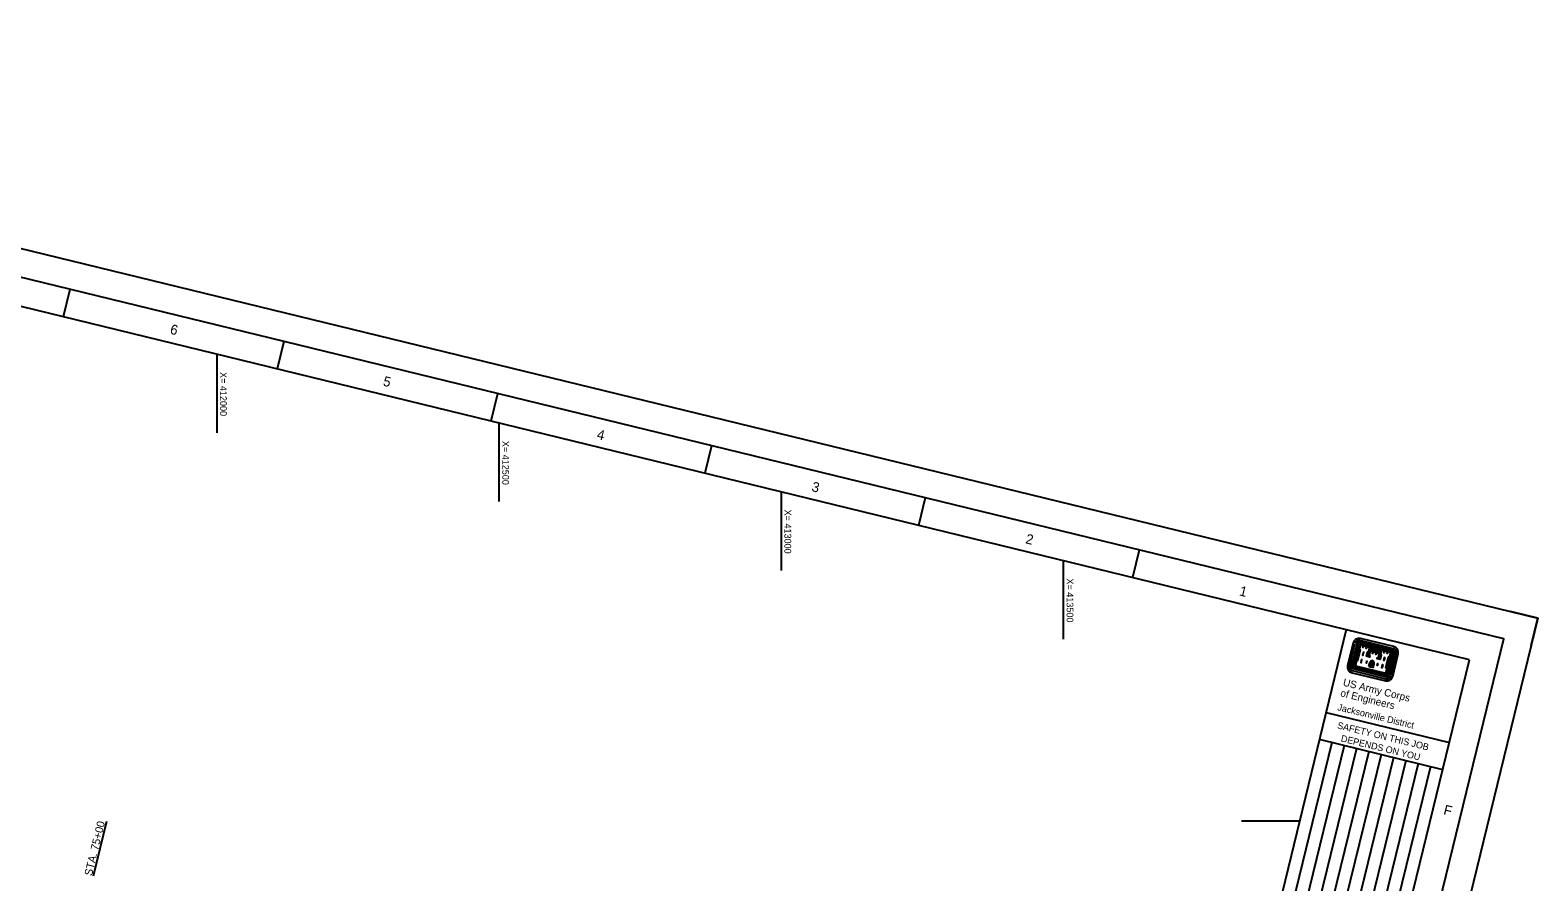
# Model space of a CAD drawing. Extents: x 409260 to 414340, y 1188556 to 1192902.
# Drawn here: x 411669 to 414340, y 1191392 to 1192902 of the extents above; entities that cross this region are included whole.
import ezdxf

# ---------------------------------------------------------------- set-up
doc = ezdxf.new("R2010")
doc.units = 0
for name, color, linetype in [('G-ANNO-NPLT', 7, 'Continuous'), ('G-ANNO-TEXT-LOGO', 7, 'Continuous'), ('G-ANNO-TEXT-TTLB', 7, 'Continuous'), ('G-ANNO-TTLB', 7, 'Continuous'), ('V-ALGN-TEXT', 7, 'Continuous'), ('V-TOPO-COOR-STAT', 7, 'Continuous')]:
    doc.layers.add(name, color=color, linetype=linetype)

msp = doc.modelspace()

# ---------------------------------------------------------------- linework, layer by layer
at = {"layer": 'G-ANNO-NPLT'}
msp.add_lwpolyline([(410065.6, 1192901.9), (414340.3, 1191859.4), (413534.7, 1188556.2), (409260, 1189598.7)], close=True, dxfattribs=at)
msp.add_lwpolyline([(414328.4, 1191810.8), (414340.3, 1191859.4), (414291.7, 1191871.2)], dxfattribs=at)
at = {"layer": 'G-ANNO-TEXT-LOGO'}
for p, q in [((414012.9, 1191815.6), (414003.2, 1191775.8)), ((414006.3, 1191775), (414016, 1191814.8)), ((414019.4, 1191814), (414009.7, 1191774.2)), ((414020.3, 1191813.8), (414010.6, 1191774)), ((414021.1, 1191813.6), (414011.4, 1191773.8)), ((414022, 1191813.4), (414012.3, 1191773.6)), ((414022.8, 1191813.2), (414013.1, 1191773.4)), ((414023.7, 1191813), (414014.1, 1191773.4)), ((414024.5, 1191812.8), (414015.1, 1191774.1)), ((414023.1, 1191804.2), (414018.1, 1191783.8)), ((414023.8, 1191803.1), (414019.3, 1191784.5)), ((414082.5, 1191799.2), (414023.5, 1191813.7)), ((414082.8, 1191800.1), (414023.7, 1191814.5)), ((414082.9, 1191800.9), (414023.9, 1191815.3)), ((414083.2, 1191801.8), (414024.1, 1191816.2)), ((414083.4, 1191802.6), (414024.3, 1191817.1)), ((414025.1, 1191820.4), (414084.2, 1191806)), ((414084.9, 1191809.1), (414025.9, 1191823.5)), ((414042.6, 1191802.8), (414060.6, 1191798.4)), ((414042.8, 1191803.7), (414060.8, 1191799.3)), ((414043, 1191804.5), (414061, 1191800.1)), ((414043.2, 1191805.4), (414061.2, 1191800.9)), ((414043.4, 1191806.2), (414061.5, 1191801.8)), ((414043.6, 1191807), (414061.6, 1191802.6)), ((414043.8, 1191807.9), (414061.9, 1191803.5)), ((414041, 1191773.9), (414042.5, 1191780.4)), ((414041.7, 1191773.7), (414043.3, 1191780.2)), ((414042.6, 1191773.5), (414044.2, 1191780)), ((414043.5, 1191773.3), (414045.1, 1191779.8)), ((414044.3, 1191773.1), (414045.8, 1191779.6)), ((414045.4, 1191772.8), (414047, 1191779.3)), ((414046.2, 1191772.6), (414047.8, 1191779.1)), ((414047.1, 1191772.4), (414048.7, 1191778.9)), ((414047.9, 1191772.2), (414049.5, 1191778.7)), ((414048.7, 1191772), (414050.3, 1191778.5)), ((414081.2, 1191798.9), (414071.8, 1191760.3)), ((414082, 1191798.8), (414072.4, 1191759.2)), ((414077.4, 1191790), (414072.9, 1191771.4)), ((414082.9, 1191798.5), (414073.2, 1191758.7)), ((414078.5, 1191790.6), (414073.5, 1191770.4)), ((414083.8, 1191798.3), (414074, 1191758.5)), ((414084.5, 1191798.1), (414074.8, 1191758.3)), ((414085.4, 1191797.9), (414075.7, 1191758.1)), ((414086.3, 1191797.7), (414076.6, 1191757.9)), ((414089.6, 1191796.9), (414079.9, 1191757.1)), ((414083.1, 1191756.3), (414092.8, 1191796.1)), ((414011.1, 1191762.7), (414070.1, 1191748.3)), ((414070.9, 1191751.5), (414011.8, 1191766)), ((414071.7, 1191754.9), (414012.7, 1191769.4)), ((414071.9, 1191755.7), (414012.9, 1191770.1)), ((414072.1, 1191756.6), (414013.1, 1191771)), ((414072.4, 1191757.5), (414013.3, 1191771.9)), ((414072.5, 1191758.2), (414013.5, 1191772.7)), ((414072.4, 1191759.2), (414014.1, 1191773.4)), ((414071.8, 1191760.3), (414015.1, 1191774.1)), ((414041, 1191773.9), (414048.7, 1191772))]:
    msp.add_line(p, q, dxfattribs=at)
for points in [[(414025.2, 1191812.6), (414023.3, 1191804.9), (414024.6, 1191802.9), (414020, 1191784.3), (414018, 1191783), (414015.9, 1191774.5), (414071.3, 1191761), (414073.3, 1191769.5), (414072, 1191771.7), (414076.5, 1191790.2), (414078.7, 1191791.4), (414080.6, 1191799.1), (414073.3, 1191800.9), (414067.6, 1191802.3), (414062.4, 1191803.5), (414060.5, 1191795.9), (414062, 1191793.8), (414060.3, 1191787), (414056.2, 1191788), (414056.4, 1191788.6), (414058.6, 1191790), (414060.4, 1191797.5), (414053.1, 1191799.3), (414047.5, 1191800.7), (414042.3, 1191801.9), (414040.5, 1191794.4), (414041.8, 1191792.2), (414041.7, 1191791.5), (414037.6, 1191792.5), (414039.2, 1191799.3), (414041.4, 1191800.5), (414043.3, 1191808.2), (414036, 1191810), (414030.3, 1191811.4), (414025.2, 1191812.6)], [(414025.7, 1191811.6), (414024.2, 1191805.1), (414025.5, 1191803), (414020.8, 1191783.7), (414018.6, 1191782.4), (414016.9, 1191775.2), (414070.7, 1191762.1), (414072.5, 1191769.3), (414071, 1191771.5), (414075.7, 1191790.7), (414078, 1191792), (414079.6, 1191798.4), (414074.3, 1191799.7), (414073.6, 1191796.7), (414073.1, 1191796.8), (414073.8, 1191799.8), (414068.7, 1191801.1), (414068, 1191798.1), (414067.6, 1191798.2), (414068.3, 1191801.2), (414063.1, 1191802.5), (414061.5, 1191796), (414062.8, 1191793.9), (414060.9, 1191786), (414055.3, 1191787.4), (414055.7, 1191789.2), (414057.9, 1191790.5), (414059.4, 1191797), (414054.2, 1191798.2), (414053.5, 1191795.2), (414053.1, 1191795.3), (414053.8, 1191798.3), (414048.6, 1191799.6), (414047.8, 1191796.6), (414047.3, 1191796.7), (414048.1, 1191799.7), (414042.9, 1191801), (414041.4, 1191794.6), (414042.7, 1191792.4), (414042.2, 1191790.5), (414036.6, 1191791.9), (414038.5, 1191799.8), (414040.7, 1191801.1), (414042.3, 1191807.5), (414037.1, 1191808.8), (414036.4, 1191805.8), (414035.9, 1191805.9), (414036.6, 1191808.9), (414031.4, 1191810.2), (414030.6, 1191807.2), (414030.3, 1191807.3), (414031, 1191810.3), (414025.7, 1191811.6)], [(414028, 1191786.3), (414026.6, 1191780.6), (414027.2, 1191780.4), (414028.6, 1191786.2), (414028, 1191786.3)], [(414031.2, 1191799.2), (414029.8, 1191793.6), (414030.4, 1191793.4), (414031.8, 1191799.1), (414031.2, 1191799.2)], [(414037, 1191784.1), (414036, 1191780.1), (414036.5, 1191780), (414037.4, 1191784), (414037, 1191784.1)], [(414040.6, 1191799.1), (414040, 1191798.7), (414038.7, 1191793.2), (414040.5, 1191792.7), (414039.5, 1191794.3), (414040.7, 1191799.2)], [(414057, 1191779.2), (414056, 1191775.3), (414055.5, 1191775.4), (414056.5, 1191779.4), (414057, 1191779.2)], [(414060.6, 1191794.2), (414061, 1191793.6), (414059.6, 1191788.1), (414057.9, 1191788.5), (414059.4, 1191789.5), (414060.6, 1191794.3)], [(414065.8, 1191777.1), (414064.4, 1191771.3), (414063.9, 1191771.5), (414065.3, 1191777.2), (414065.8, 1191777.1)], [(414069, 1191790), (414067.6, 1191784.4), (414067.1, 1191784.5), (414068.5, 1191790.1), (414069, 1191790)]]:
    msp.add_lwpolyline(points, dxfattribs=at)
for centre, major_axis, start_param, end_param in [((414023.4, 1191813.1), (10.4, -2.5), 1.57078, 3.141576), ((414023.4, 1191813.1), (7.28, -1.77), 1.57078, 3.141576), ((414023.4, 1191813.1), (3.9, -0.95), 1.57078, 3.141576), ((414023.4, 1191813.1), (3.06, -0.75), 1.57078, 3.141576), ((414023.4, 1191813.1), (2.22, -0.54), 1.57078, 3.141576), ((414023.4, 1191813.1), (1.37, -0.33), 1.57078, 3.141576), ((414023.4, 1191813.1), (0.53, -0.129), 1.57078, 3.141576), ((414082.3, 1191798.7), (7.28, -1.77), 6.28317, 7.853966), ((414082.3, 1191798.7), (10.4, -2.5), 6.283169, 7.853965), ((414047.8, 1191778.7), (-5.4, 1.32), 4.985832, 6.214359), ((414047.8, 1191778.7), (-4.55, 1.11), 4.947465, 6.21436), ((414047.8, 1191778.7), (-3.71, 0.9), 4.947465, 6.21436), ((414047.8, 1191778.7), (-2.87, 0.7), 4.947465, 6.21436), ((414044.8, 1191779.4), (2.02, -0.49), 0.068794, 1.335689), ((414047.8, 1191778.7), (-2.02, 0.49), 4.947465, 6.214359), ((414044.8, 1191779.4), (2.87, -0.7), 0.068794, 1.335689), ((414044.8, 1191779.4), (3.71, -0.9), 0.068795, 1.335689), ((414044.8, 1191779.4), (4.55, -1.11), 0.068795, 1.335689), ((414044.8, 1191779.4), (5.4, -1.32), 0.068795, 1.29842), ((414082.3, 1191798.7), (0.53, -0.129), 6.283169, 7.853965), ((414082.3, 1191798.7), (1.37, -0.33), 6.283169, 7.853965), ((414082.3, 1191798.7), (2.22, -0.54), 6.283169, 7.853965), ((414082.3, 1191798.7), (3.06, -0.75), 6.283169, 7.853965), ((414082.3, 1191798.7), (3.9, -0.95), 6.283169, 7.853965), ((414013.6, 1191773.2), (-10.4, 2.5), 6.28317, 7.853966), ((414013.6, 1191773.2), (-7.28, 1.77), 6.28317, 7.853966), ((414013.6, 1191773.2), (-3.9, 0.95), 6.28317, 7.853966), ((414013.6, 1191773.2), (-3.06, 0.75), 6.28317, 7.853966), ((414013.6, 1191773.2), (-2.22, 0.54), 6.28317, 7.853966), ((414013.6, 1191773.2), (-1.37, 0.33), 6.28317, 7.853966), ((414013.6, 1191773.2), (-0.53, 0.129), 6.28317, 7.853966), ((414072.6, 1191758.8), (10.4, -2.5), 4.712373, 6.28317), ((414072.6, 1191758.8), (-7.28, 1.77), 1.570781, 3.141577), ((414072.6, 1191758.8), (3.9, -0.95), 4.712373, 6.28317), ((414072.6, 1191758.8), (3.06, -0.75), 4.712373, 6.28317), ((414072.6, 1191758.8), (2.22, -0.54), 4.712373, 6.28317), ((414072.6, 1191758.8), (1.37, -0.33), 4.712373, 6.28317), ((414072.6, 1191758.8), (0.53, -0.129), 4.712373, 6.28317)]:
    msp.add_ellipse(centre, major_axis=major_axis, ratio=0.99964, start_param=start_param, end_param=end_param, dxfattribs=at)
at = {"layer": 'G-ANNO-TTLB'}
for p, q in [((411739.3, 1192442.2), (411727.5, 1192393.6)), ((412118.2, 1192349.8), (412106.4, 1192301.2)), ((412497.1, 1192257.4), (412485.3, 1192208.8)), ((412876, 1192165), (412864.2, 1192116.4)), ((413254.9, 1192072.6), (413243.1, 1192024)), ((413633.8, 1191980.2), (413621.9, 1191931.6)), ((414000.8, 1191839.2), (413242.6, 1188730.4)), ((413965, 1191692.3), (414183.6, 1191639)), ((413952.8, 1191644.7), (414171.4, 1191591.4)), ((413975, 1191639.3), (413776.5, 1190825.2)), ((413996.9, 1191634), (413798.4, 1190819.9)), ((414018.8, 1191628.6), (413820.2, 1190814.6)), ((414040.6, 1191623.3), (413842.1, 1190809.3)), ((414062.5, 1191618), (413863.9, 1190803.9)), ((414084.3, 1191612.6), (413885.8, 1190798.6)), ((414106.2, 1191607.3), (413907.7, 1190793.3)), ((414128.1, 1191602), (413929.5, 1190787.9)), ((414149.9, 1191596.7), (413951.4, 1190782.6))]:
    msp.add_line(p, q, dxfattribs=at)
for points in [[(409320.4, 1189635.4), (413498, 1188616.6), (414279.8, 1191822.7), (410102.3, 1192841.4)], [(414219.4, 1191785.9), (410211.9, 1192763.3), (409453.7, 1189654.4), (413461.3, 1188677.1)]]:
    msp.add_lwpolyline(points, close=True, dxfattribs=at)
at = {"layer": 'V-ALGN-TEXT'}
msp.add_line((411781.3, 1191402.7), (411805, 1191499.8), dxfattribs=at)
at = {"layer": 'V-TOPO-COOR-STAT'}
for p, q in [((412000, 1192188), (412000, 1192326.9)), ((412500, 1192066), (412500, 1192205)), ((413000, 1191944.1), (413000, 1192083.1)), ((413500, 1191822.2), (413500, 1191961.1)), ((413815.1, 1191500), (413918.1, 1191500))]:
    msp.add_line(p, q, dxfattribs=at)

# ---------------------------------------------------------------- texts
at = {"layer": 'G-ANNO-TEXT-TTLB'}
for s, height, p in [('US Army Corps', 13.086, (413994.1, 1191740)), ('of Engineers', 13.086, (413989.5, 1191721.2)), ('Jacksonville District', 11.9, (413984.5, 1191696.4)), ('SAFETY ON THIS JOB', 11.9, (413984, 1191664.2)), ('DEPENDS ON YOU', 11.9, (413990.4, 1191641.1))]:
    msp.add_text(s, height=height, rotation=346.2946, dxfattribs=at).set_placement(p)
at = {"layer": 'G-ANNO-TTLB'}
for s, p in [('6', (411915.6, 1192363.9)), ('5', (412293, 1192271.9)), ('4', (412671.8, 1192177.6)), ('3', (413052.4, 1192084.8)), ('2', (413431.4, 1191992.4)), ('1', (413810.2, 1191900)), ('F', (414172, 1191512))]:
    msp.add_text(s, height=17.5, rotation=346.2946, dxfattribs=at).set_placement(p)
at = {"layer": 'V-ALGN-TEXT'}
msp.add_text('STA. 75+00', height=13.92, rotation=76.2946, dxfattribs=at).set_placement((411778.2, 1191401.7))
at = {"layer": 'V-TOPO-COOR-STAT'}
for s, p in [('X= 412000', (412005.3, 1192295.8)), ('X= 412500', (412505.3, 1192173.8)), ('X= 413000', (413005.3, 1192051.9)), ('X= 413500', (413505.3, 1191929.9))]:
    msp.add_text(s, height=12, rotation=270, dxfattribs=at).set_placement(p)

doc.saveas('drawing.dxf')
